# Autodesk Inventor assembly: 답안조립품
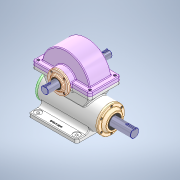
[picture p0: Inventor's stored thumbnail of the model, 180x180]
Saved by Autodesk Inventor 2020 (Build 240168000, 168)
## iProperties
Created: 2023-12
Part Number: 답안조립품
Document SubType Name: Assembly
Designer: oem
Mass: 22059.2 g
Surface Area: 7844.02 cm^2
Volume: 4946.5 cm^3
Density: 4.45957 g/cm^3
Author: oem
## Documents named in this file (14)
- C:\Users\oem\Desktop\631208V1009\답안조립품.iam
- C:\Users\oem\Desktop\631208V1009\본체.ipt
- C:\Users\oem\Desktop\631208V1009\깊은 홈 볼 베어링 6209.ipt
- C:\Users\oem\Desktop\631208V1009\웜 샤프트.ipt
- C:\Users\oem\Desktop\631208V1009\뒤커버.ipt
- C:\Users\oem\Desktop\631208V1009\앞커버.ipt
- C:\Users\oem\Desktop\631208V1009\육각 소켓 머리 볼트 M5 x 12.ipt
- C:\Users\oem\Desktop\631208V1009\오일 실 35 55 11.ipt
- C:\Users\oem\Desktop\631208V1009\깊은 홈 볼 베어링 6206.ipt
- C:\Users\oem\Desktop\631208V1009\웜 휠.ipt
- C:\Users\oem\Desktop\631208V1009\본체 커버.ipt
- C:\Users\oem\Desktop\631208V1009\육각 소켓 머리 볼트 M6 x 20.ipt
- C:\Users\oem\Desktop\631208V1009\서브커버.ipt
- C:\Users\oem\Desktop\631208V1009\오일 실 30 42 7.ipt
